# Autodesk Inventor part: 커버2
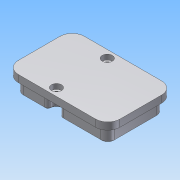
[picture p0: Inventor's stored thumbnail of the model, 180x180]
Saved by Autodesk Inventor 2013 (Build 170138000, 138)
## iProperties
Company: 한국ATC센터
Created: 2015-04
Part Number: 커버2
Document SubType Name: Modeling
Designer: KYOUNG IL JANG
Density: 2.71 g/cm^3
Material: 알루미늄-6061
Mass: 222.992 g
Surface Area: 213.51 cm^2
Volume: 82.2849 cm^3
Author: KYOUNG IL JANG
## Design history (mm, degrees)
node "작업 평면1"
sketch "스케치1"
  geometry: L1 (-16.986, 27.5)-(-38, 27.5) reference; L2 (-45, 20.5)-(-45, -20.5) reference; L3 (-38, -27.5)-(-16.986, -27.5) reference; L4 (0.986, -27.5)-(38, -27.5) reference; L5 (45, -20.5)-(45, 20.5) reference; L6 (38, 27.5)-(0.986, 27.5) reference; C1 r 25 at (15, 0); A1 r 3 centre (-16.986, 24.5) between (-13.991, 24.667) and (-16.986, 27.5) reference; A2 r 7 centre (-38, 20.5) between (-38, 27.5) and (-45, 20.5) reference; A3 r 7 centre (-38, -20.5) between (-45, -20.5) and (-38, -27.5) reference; A4 r 3 centre (-16.986, -24.5) between (-16.986, -27.5) and (-13.991, -24.667) reference; A5 r 6 centre (-8, -25) between (-2.009, -24.667) and (-13.991, -24.667) reference; A6 r 3 centre (0.986, -24.5) between (-2.009, -24.667) and (0.986, -27.5) reference; A7 r 7 centre (38, -20.5) between (38, -27.5) and (45, -20.5) reference; A8 r 7 centre (38, 20.5) between (45, 20.5) and (38, 27.5) reference; A9 r 3 centre (0.986, 24.5) between (0.986, 27.5) and (-2.009, 24.667) reference; A10 r 6 centre (-8, 25) between (-13.991, 24.667) and (-2.009, 24.667) reference; 1 further point
  constraints: 20 point on circle, 12 end point, 11 centre point, 4 horizontal, 2 vertical, 36 other
extrude "돌출1" new body sketch "스케치1" distance "d0" = 14; taper "d1" = 0 deg
sketch "스케치2"
  geometry: L1 (38, -32.5)-(-38, -32.5) reference; L2 (50, 20.5)-(50, -20.5) reference; L3 (-38, 32.5)-(38, 32.5) reference; L4 (-50, -20.5)-(-50, 20.5) reference; A1 r 12 centre (38, -20.5) between (38, -32.5) and (50, -20.5) reference; A2 r 12 centre (38, 20.5) between (50, 20.5) and (38, 32.5) reference; A3 r 12 centre (-38, 20.5) between (-38, 32.5) and (-50, 20.5) reference; A4 r 12 centre (-38, -20.5) between (-50, -20.5) and (-38, -32.5) reference; 1 further point
extrude "돌출2" join sketch "스케치2" distance "d2" = 7; taper "d3" = 0 deg
sketch "스케치3"
  geometry: C1 r 2.458 at (-8, 25) reference; C2 r 2.458 at (-8, -25) reference; 1 further point
hole "구멍1" sketch "스케치3" at (-8, -25), (-8, 25) diameter "d4" = 6; stored, may be unused: countersink angle "d8" = 90 deg, drill point angle "d10" = 118 deg; dims "d5" = 6, "d6" = 10, "d7" = 5, "d9" = 8
fillet "모깎기1" dims "d11" = 0.3
chamfer "모따기1" distance "d12" = 1; stored, may be unused: second distance "d13" = 2, angle "d14" = 45 deg
node "솔리드1"
node "참조2"
node "참조3"
node "참조4"
node "참조5"
node "참조6"
node "참조7"
node "참조8"
node "참조9"
node "참조10"
node "참조11"
